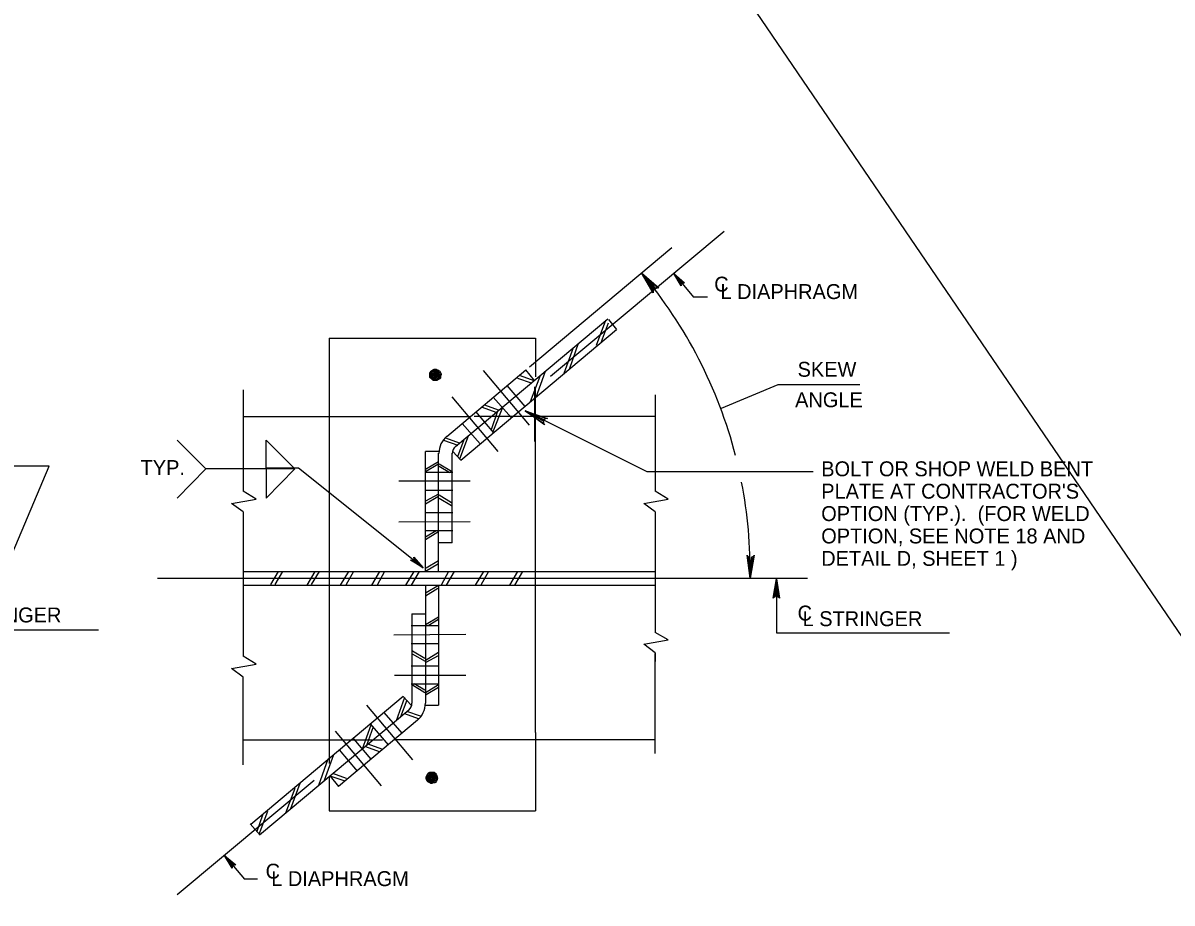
# Model space of a CAD drawing. Extents: x 634656 to 641360, y 298715 to 301183.
# Drawn here: x 640609.6 to 640840.5, y 299069.3 to 299246.2 of the extents above; entities that cross this region are included whole.
import ezdxf

# ---------------------------------------------------------------- set-up
doc = ezdxf.new("R2010")
doc.units = 0
doc.layers.add('1', color=7, linetype='Continuous')
doc.layers.add('2', color=7, linetype='Continuous')

msp = doc.modelspace()

# ---------------------------------------------------------------- linework, layer by layer
at = {"layer": '1'}
msp.add_line((640203.02, 300061.47), (641094.36, 298753.08), dxfattribs=at)
msp.add_lwpolyline([(640760.53, 299130.76), (640760.79, 299130.9), (640760.99, 299134.45), (640760.53, 299130.76), (640760.36, 299130.57), (640760.99, 299134.45), (640761.16, 299130.9), (640761.43, 299130.77), (640760.99, 299134.45), (640761.6, 299130.57), (640761.43, 299130.77)], dxfattribs=at)
at = {"layer": '2'}
for p, q in [((640715.61, 299175.2), (640750.49, 299204.33)), ((640711.36, 299177.08), (640739.99, 299201.08)), ((640740.36, 299195.83), (640744.36, 299191.08)), ((640747.11, 299191.08), (640744.36, 299191.08)), ((640696.49, 299161.08), (640727.11, 299186.7)), ((640724.86, 299181.45), (640726.74, 299186.45)), ((640727.24, 299186.58), (640728.86, 299184.58)), ((640697.61, 299158.33), (640728.86, 299184.58)), ((640725.86, 299182.2), (640727.24, 299185.95)), ((640671.11, 299182.83), (640671.11, 299165.45)), ((640671.11, 299182.83), (640712.61, 299182.83)), ((640712.61, 299182.83), (640712.61, 299175.08)), ((640719.49, 299176.83), (640721.24, 299181.83)), ((640718.36, 299175.83), (640720.24, 299180.95)), ((640694.74, 299163.08), (640710.61, 299176.45)), ((640711.36, 299165.33), (640702.11, 299176.33)), ((640708.99, 299174.83), (640711.74, 299173.83)), ((640709.49, 299175.33), (640712.24, 299174.33)), ((640712.36, 299174.33), (640710.61, 299176.45)), ((640711.61, 299170.08), (640713.49, 299175.2)), ((640712.74, 299170.95), (640714.61, 299176.2)), ((640653.86, 299172.45), (640653.86, 299152.08)), ((640710.49, 299169.08), (640706.86, 299173.33)), ((640712.36, 299173.08), (640712.36, 299162.08)), ((640712.61, 299103.58), (640712.61, 299172.7)), ((640761.24, 299173.45), (640749.86, 299168.7)), ((640777.74, 299173.45), (640761.24, 299173.45)), ((640705.11, 299160.08), (640695.86, 299171.08)), ((640707.74, 299166.83), (640704.11, 299170.95)), ((640708.61, 299171.2), (640708.61, 299171.2)), ((640736.61, 299171.45), (640736.61, 299152.08)), ((640704.24, 299163.83), (640700.61, 299168.08)), ((640701.86, 299168.95), (640704.61, 299167.95)), ((640702.36, 299169.45), (640705.11, 299168.45)), ((640703.74, 299164.45), (640704.99, 299168.2)), ((640704.11, 299164.08), (640705.99, 299168.95)), ((640734.99, 299155.95), (640710.49, 299168.2)), ((640653.86, 299167.08), (640699.49, 299167.08)), ((640701.49, 299161.58), (640697.86, 299165.7)), ((640736.61, 299167.08), (640700.24, 299167.08)), ((640671.11, 299165.45), (640671.11, 299097.33)), ((640697.36, 299158.58), (640699.11, 299163.2)), ((640694.11, 299162.33), (640696.99, 299161.33)), ((640694.49, 299162.83), (640697.24, 299161.83)), ((640696.99, 299159.08), (640698.24, 299162.45)), ((640690.49, 299135.95), (640690.49, 299160.08)), ((640693.24, 299160.08), (640690.49, 299160.08)), ((640693.11, 299135.95), (640693.11, 299159.7)), ((640695.86, 299141.7), (640695.86, 299159.7)), ((640697.61, 299158.33), (640695.99, 299160.08)), ((640614.86, 299157.08), (640573.11, 299157.08)), ((640605.61, 299135.2), (640614.86, 299157.08)), ((640664.24, 299156.58), (640646.36, 299156.58)), ((640658.49, 299156.58), (640658.49, 299150.7)), ((640658.49, 299150.7), (640664.24, 299156.58)), ((640664.99, 299156.7), (640658.61, 299156.7)), ((640689.99, 299136.7), (640664.99, 299156.7)), ((640693.11, 299157.95), (640690.49, 299156.45)), ((640692.99, 299157.45), (640690.49, 299155.95)), ((640693.24, 299157.58), (640695.74, 299156.08)), ((640693.24, 299157.08), (640695.36, 299155.83)), ((640699.49, 299154.08), (640685.11, 299154.08)), ((640695.99, 299155.83), (640690.49, 299155.83)), ((640693.11, 299155.83), (640693.11, 299155.83)), ((640768.36, 299155.95), (640734.99, 299155.95)), ((640656.49, 299150.45), (640653.86, 299152.08)), ((640695.99, 299152.2), (640690.49, 299152.2)), ((640739.24, 299150.45), (640736.61, 299152.08)), ((640651.49, 299149.58), (640656.49, 299150.45)), ((640653.86, 299147.95), (640651.49, 299149.58)), ((640693.11, 299151.45), (640690.49, 299150.08)), ((640692.99, 299150.95), (640690.49, 299149.45)), ((640693.24, 299151.33), (640695.74, 299149.83)), ((640693.24, 299150.7), (640695.74, 299149.2)), ((640734.36, 299149.58), (640739.24, 299150.45)), ((640736.61, 299147.95), (640734.36, 299149.58)), ((640653.86, 299147.95), (640653.86, 299118.95)), ((640695.99, 299147.7), (640690.49, 299147.7)), ((640736.61, 299147.95), (640736.61, 299123.7)), ((640699.49, 299145.95), (640685.11, 299145.83)), ((640695.99, 299144.08), (640690.49, 299144.08)), ((640692.61, 299144.08), (640690.49, 299142.83)), ((640692.99, 299143.83), (640690.49, 299142.33)), ((640695.86, 299141.7), (640693.11, 299141.7)), ((640693.11, 299138.08), (640690.61, 299136.58)), ((640653.86, 299135.95), (640736.61, 299135.95)), ((640660.86, 299135.95), (640659.36, 299133.33)), ((640661.74, 299135.95), (640660.24, 299133.33)), ((640668.24, 299135.95), (640666.61, 299133.2)), ((640669.11, 299135.95), (640667.49, 299133.33)), ((640674.99, 299135.95), (640673.36, 299133.2)), ((640675.99, 299135.95), (640674.49, 299133.2)), ((640681.24, 299135.95), (640679.61, 299133.2)), ((640682.24, 299135.95), (640680.74, 299133.2)), ((640688.11, 299135.95), (640686.49, 299133.2)), ((640689.24, 299135.95), (640687.61, 299133.2)), ((640693.11, 299137.45), (640690.49, 299135.95)), ((640695.11, 299135.95), (640693.61, 299133.2)), ((640696.24, 299135.95), (640694.61, 299133.2)), ((640702.11, 299135.95), (640700.49, 299133.2)), ((640703.11, 299135.95), (640701.61, 299133.2)), ((640708.99, 299135.95), (640707.36, 299133.2)), ((640709.99, 299135.95), (640708.36, 299133.2)), ((640636.61, 299134.58), (640767.24, 299134.58)), ((640653.86, 299133.2), (640736.61, 299133.2)), ((640671.24, 299134.95), (640671.24, 299134.95)), ((640690.49, 299133.2), (640690.49, 299109.45)), ((640690.61, 299131.7), (640693.11, 299133.2)), ((640693.11, 299133.2), (640693.11, 299109.08)), ((640760.99, 299134.45), (640760.99, 299123.58)), ((640690.49, 299131.08), (640692.99, 299132.58)), ((640687.74, 299127.45), (640690.49, 299127.45)), ((640687.74, 299127.45), (640687.74, 299109.45)), ((640690.61, 299125.33), (640693.11, 299126.83)), ((640690.99, 299125.08), (640693.11, 299126.33)), ((640588.01, 299124.2), (640624.76, 299124.2)), ((640687.61, 299125.08), (640693.11, 299125.08)), ((640684.11, 299123.2), (640698.61, 299123.33)), ((640734.36, 299121.33), (640739.24, 299122.2)), ((640739.24, 299122.2), (640736.61, 299123.7)), ((640760.99, 299123.58), (640795.74, 299123.58)), ((640687.61, 299121.45), (640693.11, 299121.45)), ((640690.36, 299118.45), (640687.86, 299119.95)), ((640690.49, 299117.83), (640687.86, 299119.33)), ((640690.61, 299118.2), (640693.11, 299119.7)), ((640736.61, 299119.58), (640734.36, 299121.33)), ((640736.61, 299119.58), (640736.61, 299117.83)), ((640736.61, 299099.33), (640736.61, 299119.45)), ((640651.49, 299116.45), (640656.49, 299117.33)), ((640656.49, 299117.33), (640653.86, 299118.95)), ((640690.61, 299117.7), (640693.11, 299119.08)), ((640653.86, 299114.7), (640651.49, 299116.45)), ((640653.86, 299097.08), (640653.86, 299114.7)), ((640684.24, 299115.08), (640698.61, 299115.08)), ((640687.61, 299116.95), (640693.11, 299116.95)), ((640687.61, 299113.33), (640693.11, 299113.33)), ((640690.36, 299111.58), (640687.86, 299113.08)), ((640690.36, 299112.08), (640688.24, 299113.33)), ((640690.49, 299113.33), (640690.49, 299113.33)), ((640690.61, 299111.7), (640693.11, 299113.2)), ((640690.61, 299111.2), (640693.11, 299112.7)), ((640685.99, 299110.83), (640655.36, 299085.08)), ((640686.24, 299110.58), (640684.61, 299105.95)), ((640686.74, 299110.08), (640685.49, 299106.7)), ((640685.99, 299110.83), (640687.61, 299109.08)), ((640687.11, 299108.08), (640657.11, 299082.95)), ((640678.61, 299109.08), (640687.86, 299098.08)), ((640689.49, 299106.83), (640686.74, 299107.83)), ((640690.49, 299109.08), (640693.11, 299109.08)), ((640688.86, 299106.08), (640672.99, 299092.7)), ((640682.11, 299107.58), (640685.74, 299103.45)), ((640689.11, 299106.33), (640686.36, 299107.33)), ((640672.36, 299103.83), (640681.61, 299092.83)), ((640679.49, 299105.08), (640677.74, 299100.2)), ((640679.99, 299104.7), (640678.61, 299100.95)), ((640679.36, 299105.33), (640682.99, 299101.08)), ((640712.61, 299103.58), (640712.61, 299087.83)), ((640653.86, 299102.08), (640681.86, 299102.08)), ((640675.99, 299102.33), (640679.49, 299098.2)), ((640681.74, 299100.2), (640678.99, 299101.2)), ((640736.61, 299102.08), (640684.24, 299102.08)), ((640671.99, 299099.08), (640670.11, 299093.95)), ((640673.11, 299100.08), (640676.74, 299095.83)), ((640681.24, 299099.7), (640678.49, 299100.7)), ((640670.86, 299098.2), (640668.99, 299092.95)), ((640674.99, 299097.95), (640674.99, 299097.95)), ((640668.11, 299093.95), (640640.61, 299070.95)), ((640671.11, 299094.58), (640671.11, 299087.83)), ((640671.36, 299094.83), (640672.99, 299092.7)), ((640674.11, 299093.83), (640671.36, 299094.83)), ((640674.61, 299094.33), (640671.86, 299095.33)), ((640664.24, 299092.33), (640662.36, 299087.33)), ((640665.24, 299093.33), (640663.36, 299088.2)), ((640658.74, 299087.7), (640656.99, 299083.08)), ((640671.11, 299087.83), (640712.61, 299087.83)), ((640657.24, 299082.95), (640655.24, 299085.2)), ((640657.74, 299086.95), (640656.61, 299083.7)), ((640650.11, 299078.83), (640654.11, 299074.08)), ((640656.74, 299074.08), (640654.11, 299074.08))]:
    msp.add_line(p, q, dxfattribs=at)
for points in [[(640736.24, 299192.33), (640736.36, 299192.58), (640733.86, 299195.95), (640736.24, 299192.33), (640736.24, 299191.95), (640733.86, 299195.95), (640736.74, 299192.83), (640737.11, 299192.95), (640733.86, 299195.95), (640737.36, 299192.95), (640737.11, 299192.95)], [(640741.86, 299193.58), (640741.86, 299193.7), (640740.36, 299195.83), (640741.86, 299193.58), (640741.86, 299193.33), (640740.36, 299195.83), (640742.11, 299193.95), (640742.36, 299193.95), (640740.36, 299195.83), (640742.49, 299193.95), (640742.36, 299193.95)], [(640714.24, 299165.7), (640714.24, 299166.08), (640710.49, 299168.2), (640714.24, 299165.7), (640714.36, 299165.45), (640710.49, 299168.2), (640714.36, 299166.45), (640714.61, 299166.7), (640710.49, 299168.2), (640714.99, 299166.7), (640714.61, 299166.7)], [(640640.61, 299150.7), (640646.36, 299156.58), (640640.61, 299162.33)], [(640658.49, 299156.58), (640658.49, 299162.33), (640664.24, 299156.58), (640658.49, 299156.58)], [(640688.11, 299138.7), (640688.11, 299138.45), (640689.99, 299136.7), (640688.11, 299138.7), (640688.11, 299138.83), (640689.99, 299136.7), (640687.86, 299138.2), (640687.74, 299138.2), (640689.99, 299136.7), (640687.49, 299138.2), (640687.74, 299138.2)], [(640756.36, 299138.95), (640755.99, 299138.83), (640755.74, 299134.58), (640756.36, 299138.95), (640756.49, 299139.2), (640755.74, 299134.58), (640755.61, 299138.83), (640755.24, 299138.95), (640755.74, 299134.58), (640755.11, 299139.2), (640755.24, 299138.95)], [(640651.61, 299076.58), (640651.74, 299076.7), (640650.11, 299078.83), (640651.61, 299076.58), (640651.61, 299076.33), (640650.11, 299078.83), (640651.86, 299076.95), (640652.11, 299076.95), (640650.11, 299078.83), (640652.36, 299076.95), (640652.11, 299076.95)]]:
    msp.add_lwpolyline(points, dxfattribs=at)
for centre, radius, start, end in [((640662.4, 299135.96), 93.33, 14.4328, 40.0036), ((640697.67, 299159.68), 4.5, 129.9975, 180), ((640697.67, 299159.69), 1.8, 130.0014, 180), ((640662.4, 299135.96), 93.33, 359.1528, 11.0832), ((640685.97, 299109.47), 1.8, 310.0014, 0), ((640685.97, 299109.47), 4.5, 309.9975, 0)]:
    msp.add_arc(centre, radius, start, end, dxfattribs=at)
for points in [[(640692.49, 299175.45), (640692.36, 299175.45), (640692.36, 299175.58), (640692.49, 299175.58), (640692.61, 299175.45), (640692.49, 299175.2), (640692.36, 299175.2), (640692.24, 299175.33), (640692.24, 299175.58), (640692.36, 299175.7), (640692.49, 299175.83), (640692.74, 299175.7), (640692.86, 299175.45), (640692.74, 299175.2), (640692.61, 299175.08), (640692.24, 299175.08), (640692.11, 299175.2), (640691.99, 299175.45), (640692.11, 299175.7), (640692.24, 299175.83), (640692.36, 299175.95), (640692.61, 299175.95), (640692.86, 299175.95), (640692.99, 299175.7), (640692.99, 299175.33), (640692.86, 299175.08), (640692.61, 299174.83), (640692.36, 299174.83), (640692.11, 299174.95), (640691.86, 299175.2), (640691.86, 299175.58), (640691.99, 299175.83), (640692.24, 299175.95), (640692.49, 299176.08), (640692.86, 299176.08), (640693.11, 299175.83), (640693.24, 299175.58), (640693.11, 299175.08), (640692.86, 299174.7), (640692.49, 299174.7), (640692.11, 299174.7), (640691.86, 299174.95), (640691.74, 299175.2), (640691.74, 299175.7), (640691.86, 299176.08), (640692.24, 299176.2), (640692.49, 299176.2), (640692.86, 299176.2), (640693.11, 299176.08), (640693.36, 299175.83), (640693.36, 299175.33), (640693.24, 299174.95), (640692.99, 299174.58), (640692.61, 299174.45), (640692.24, 299174.58), (640691.74, 299174.7), (640691.61, 299174.95), (640691.49, 299175.33), (640691.49, 299175.7), (640691.74, 299176.08), (640691.99, 299176.33), (640692.24, 299176.45), (640692.49, 299176.45), (640692.86, 299176.45), (640693.11, 299176.33), (640693.36, 299176.2), (640693.49, 299175.95), (640693.61, 299175.7), (640693.61, 299175.45), (640693.49, 299175.2), (640693.49, 299174.83), (640693.24, 299174.58), (640692.99, 299174.45), (640692.74, 299174.33), (640692.36, 299174.33), (640692.11, 299174.33), (640691.86, 299174.45), (640691.61, 299174.7), (640691.36, 299174.95), (640691.36, 299175.2), (640691.36, 299175.45), (640691.36, 299175.83), (640691.61, 299176.2), (640691.74, 299176.33), (640691.99, 299176.45), (640692.24, 299176.58), (640692.61, 299176.58), (640692.86, 299176.45), (640692.99, 299176.45), (640693.24, 299176.2)], [(640691.74, 299094.45), (640691.61, 299094.58), (640691.61, 299094.7), (640691.86, 299094.7), (640691.86, 299094.45), (640691.86, 299094.33), (640691.61, 299094.33), (640691.49, 299094.45), (640691.49, 299094.7), (640691.61, 299094.83), (640691.86, 299094.83), (640692.11, 299094.7), (640692.11, 299094.58), (640691.99, 299094.2), (640691.86, 299094.08), (640691.61, 299094.08), (640691.36, 299094.33), (640691.36, 299094.45), (640691.36, 299094.7), (640691.49, 299094.95), (640691.61, 299094.95), (640691.86, 299094.95), (640692.11, 299094.95), (640692.24, 299094.7), (640692.36, 299094.45), (640692.24, 299094.08), (640691.99, 299093.95), (640691.61, 299093.95), (640691.36, 299094.08), (640691.11, 299094.33), (640691.11, 299094.7), (640691.24, 299094.95), (640691.49, 299095.08), (640691.86, 299095.2), (640692.11, 299095.08), (640692.36, 299094.95), (640692.49, 299094.58), (640692.36, 299094.08), (640692.11, 299093.83), (640691.74, 299093.7), (640691.36, 299093.83), (640691.11, 299093.95), (640690.99, 299094.33), (640690.99, 299094.7), (640691.24, 299095.08), (640691.49, 299095.33), (640691.86, 299095.33), (640692.11, 299095.33), (640692.36, 299095.2), (640692.61, 299094.95), (640692.74, 299094.45), (640692.61, 299093.95), (640692.24, 299093.7), (640691.99, 299093.58), (640691.49, 299093.58), (640691.11, 299093.7), (640690.86, 299093.95), (640690.74, 299094.33), (640690.86, 299094.83), (640690.99, 299095.08), (640691.24, 299095.33), (640691.49, 299095.45), (640691.86, 299095.45), (640692.11, 299095.45), (640692.49, 299095.33), (640692.61, 299095.2), (640692.74, 299094.95), (640692.86, 299094.7), (640692.86, 299094.58), (640692.86, 299094.2), (640692.74, 299093.95), (640692.61, 299093.7), (640692.36, 299093.45), (640691.99, 299093.45), (640691.74, 299093.33), (640691.36, 299093.45), (640691.11, 299093.58), (640690.86, 299093.7), (640690.74, 299093.95), (640690.61, 299094.33), (640690.61, 299094.58), (640690.74, 299094.95), (640690.86, 299095.2), (640691.11, 299095.45), (640691.36, 299095.58), (640691.61, 299095.58), (640691.86, 299095.58), (640692.24, 299095.58), (640692.36, 299095.45), (640692.61, 299095.33)]]:
    msp.add_spline(points, degree=3, dxfattribs=at)

# ---------------------------------------------------------------- texts
for s, p in [('C', (640748.49, 299192.2)), ('L DIAPHRAGM', (640749.74, 299190.7)), ('SKEW', (640765.24, 299175.08)), ('ANGLE', (640764.74, 299168.95)), ('TYP.', (640633.24, 299155.33)), ('BOLT OR SHOP WELD BENT', (640769.99, 299155.08)), ("PLATE AT CONTRACTOR'S", (640769.99, 299150.58)), ('OPTION (TYP.).  (FOR WELD', (640769.99, 299146.08)), ('OPTION, SEE NOTE 18 AND', (640769.99, 299141.58)), ('DETAIL D, SHEET 1 )', (640769.99, 299137.08)), ('L STRINGER', (640593.26, 299125.7)), ('C', (640765.24, 299126.08)), ('L STRINGER', (640766.24, 299124.95)), ('C', (640658.36, 299074.2)), ('L DIAPHRAGM', (640659.49, 299072.7))]:
    msp.add_text(s, height=3, dxfattribs=at).set_placement(p)

doc.saveas('drawing.dxf')
